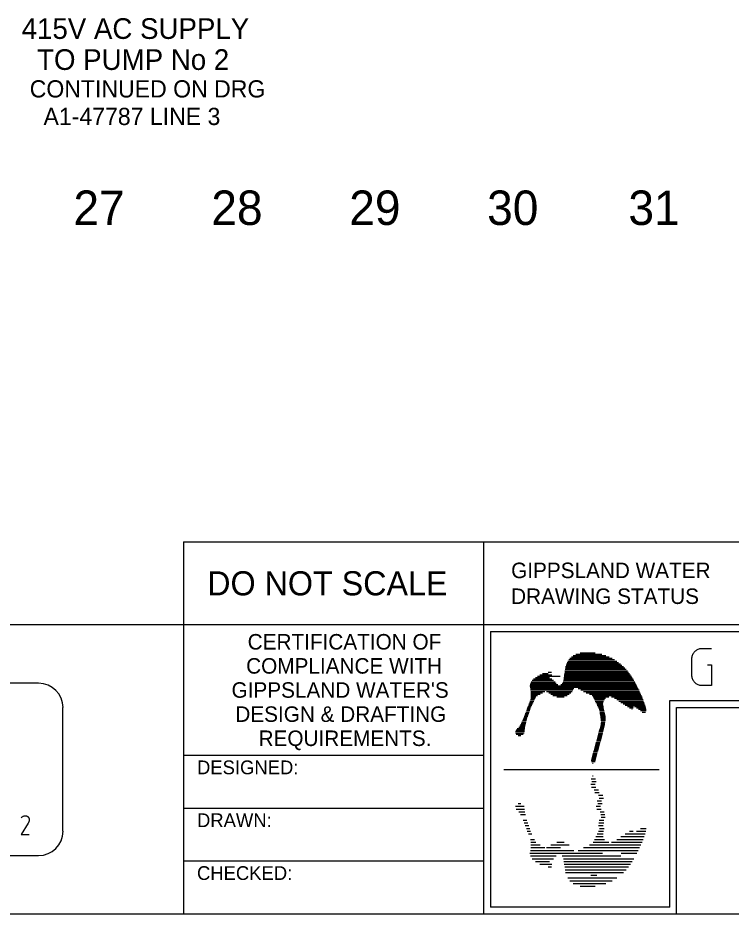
# Model space of a CAD drawing. Extents: x 0 to 841, y 0 to 594.
# Drawn here: x 568.5 to 671.9, y 15 to 145 of the extents above; entities that cross this region are included whole.
import ezdxf

# ---------------------------------------------------------------- set-up
doc = ezdxf.new("R2010")
doc.units = 0
for name, color, linetype in [('A1BORDER', 7, 'Continuous'), ('Level 1', 7, 'Continuous'), ('Level 10', 7, 'Continuous')]:
    doc.layers.add(name, color=color, linetype=linetype)

msp = doc.modelspace()

# ---------------------------------------------------------------- linework, layer by layer
at = {"layer": 'A1BORDER'}
for p, q in [((592.5, 69), (592.5, 15)), ((592.5, 69), (829, 69)), ((636, 69), (636, 15)), ((28, 57), (829, 57)), ((637, 56), (788, 56)), ((637, 56), (637, 16)), ((648.53, 52.12), (654.64, 52.12)), ((648.74, 52.32), (654.24, 52.32)), ((649.02, 52.52), (653.76, 52.52)), ((649.39, 52.72), (653.15, 52.72)), ((650.01, 52.92), (652.2, 52.92)), ((647.88, 50.72), (656.5, 50.72)), ((647.91, 50.92), (656.3, 50.92)), ((647.96, 51.12), (656.08, 51.12)), ((648.03, 51.32), (655.85, 51.32)), ((648.12, 51.52), (655.59, 51.52)), ((648.23, 51.72), (655.31, 51.72)), ((648.37, 51.92), (655, 51.92)), ((643.85, 49.52), (647.09, 49.52)), ((644.18, 49.72), (645.89, 49.72)), ((644.54, 49.92), (645.36, 49.92)), ((645.37, 50.12), (645.86, 50.12)), ((647.69, 49.52), (657.44, 49.52)), ((647.71, 49.72), (657.31, 49.72)), ((647.75, 49.92), (657.17, 49.92)), ((647.78, 50.12), (657.02, 50.12)), ((647.81, 50.32), (656.86, 50.32)), ((647.85, 50.52), (656.69, 50.52)), ((642.73, 48.12), (658.25, 48.12)), ((642.75, 48.32), (646.79, 48.32)), ((642.81, 48.52), (646.55, 48.52)), ((642.9, 48.72), (646.37, 48.72)), ((643.04, 48.92), (646.16, 48.92)), ((643.26, 49.12), (645.9, 49.12)), ((643.54, 49.32), (645.57, 49.32)), ((647.19, 48.32), (658.14, 48.32)), ((647.42, 48.52), (658.03, 48.52)), ((647.54, 48.72), (657.92, 48.72)), ((647.61, 48.92), (657.8, 48.92)), ((647.63, 49.12), (657.68, 49.12)), ((647.66, 49.32), (657.57, 49.32)), ((642.74, 47.92), (658.35, 47.92)), ((642.79, 47.72), (649.08, 47.72)), ((642.83, 47.52), (648.95, 47.52)), ((642.85, 47.31), (644.88, 47.31)), ((642.87, 47.12), (644.57, 47.12)), ((642.88, 46.92), (644.23, 46.92)), ((645.14, 47.31), (648.83, 47.31)), ((645.49, 47.12), (648.67, 47.12)), ((645.76, 46.92), (648.42, 46.92)), ((649.72, 47.72), (658.45, 47.72)), ((650.12, 47.52), (658.55, 47.52)), ((650.48, 47.31), (658.64, 47.31)), ((650.87, 47.12), (658.73, 47.12)), ((651.36, 46.92), (658.82, 46.92)), ((642.57, 45.52), (643.1, 45.52)), ((642.65, 45.72), (643.2, 45.72)), ((642.72, 45.92), (643.3, 45.92)), ((642.79, 46.12), (643.4, 46.12)), ((642.84, 46.32), (643.5, 46.32)), ((642.87, 46.52), (643.6, 46.52)), ((642.88, 46.72), (643.83, 46.72)), ((646.05, 46.72), (648.11, 46.72)), ((646.62, 46.52), (647.67, 46.52)), ((651.76, 46.72), (658.9, 46.72)), ((651.88, 46.52), (654.15, 46.52)), ((651.99, 46.32), (653.71, 46.32)), ((652.1, 46.12), (653.52, 46.12)), ((652.2, 45.92), (653.4, 45.92)), ((652.31, 45.72), (653.33, 45.72)), ((652.41, 45.52), (653.31, 45.52)), ((654.57, 46.52), (658.99, 46.52)), ((655, 46.32), (659.07, 46.32)), ((655.31, 46.12), (659.14, 46.12)), ((655.62, 45.92), (659.22, 45.92)), ((655.93, 45.72), (659.29, 45.72)), ((656.24, 45.52), (659.35, 45.52)), ((663, 46), (788, 46)), ((663, 16), (663, 46)), ((642.13, 44.32), (642.62, 44.32)), ((642.21, 44.52), (642.69, 44.52)), ((642.28, 44.72), (642.76, 44.72)), ((642.35, 44.92), (642.83, 44.92)), ((642.43, 45.12), (642.9, 45.12)), ((642.5, 45.32), (643, 45.32)), ((652.5, 45.32), (653.34, 45.32)), ((652.6, 45.12), (653.38, 45.12)), ((652.69, 44.92), (653.41, 44.92)), ((652.78, 44.72), (653.44, 44.72)), ((652.83, 44.52), (653.48, 44.52)), ((652.86, 44.32), (653.53, 44.32)), ((656.55, 45.32), (659.42, 45.32)), ((656.86, 45.12), (657.74, 45.12)), ((657.17, 44.92), (657.68, 44.92)), ((657.51, 44.72), (657.54, 44.72)), ((657.91, 45.12), (659.48, 45.12)), ((658.19, 44.92), (659.54, 44.92)), ((658.47, 44.72), (659.59, 44.72)), ((658.75, 44.52), (659.58, 44.52)), ((659.02, 44.32), (659.47, 44.32)), ((664, 45), (829, 45)), ((664, 15), (664, 45)), ((641.55, 42.92), (642.2, 42.92)), ((641.64, 43.12), (642.25, 43.12)), ((641.73, 43.32), (642.3, 43.32)), ((641.82, 43.51), (642.35, 43.51)), ((641.91, 43.72), (642.41, 43.72)), ((641.99, 43.92), (642.48, 43.92)), ((642.06, 44.12), (642.55, 44.12)), ((652.89, 44.12), (653.57, 44.12)), ((652.91, 43.92), (653.62, 43.92)), ((652.94, 43.72), (653.67, 43.72)), ((652.97, 43.51), (653.71, 43.51)), ((653, 43.32), (653.69, 43.32)), ((653.02, 43.12), (653.67, 43.12)), ((653.05, 42.92), (653.64, 42.92)), ((640.73, 41.72), (641.95, 41.72)), ((640.9, 41.92), (641.97, 41.92)), ((641.1, 42.12), (642, 42.12)), ((641.25, 42.31), (642.04, 42.31)), ((641.37, 42.52), (642.09, 42.52)), ((641.46, 42.72), (642.15, 42.72)), ((652.79, 41.72), (653.41, 41.72)), ((652.85, 41.92), (653.45, 41.92)), ((652.9, 42.12), (653.49, 42.12)), ((652.95, 42.31), (653.53, 42.31)), ((652.99, 42.52), (653.57, 42.52)), ((653.03, 42.72), (653.61, 42.72)), ((640.62, 41.32), (641.88, 41.32)), ((640.63, 41.52), (641.93, 41.52)), ((640.72, 41.12), (641.73, 41.12)), ((641.03, 40.92), (641.43, 40.92)), ((652.41, 40.32), (653.04, 40.32)), ((652.47, 40.52), (653.1, 40.52)), ((652.52, 40.72), (653.15, 40.72)), ((652.57, 40.92), (653.2, 40.92)), ((652.63, 41.12), (653.26, 41.12)), ((652.68, 41.32), (653.31, 41.32)), ((652.74, 41.52), (653.37, 41.52)), ((652.09, 39.12), (652.72, 39.12)), ((652.14, 39.32), (652.77, 39.32)), ((652.2, 39.52), (652.82, 39.52)), ((652.25, 39.72), (652.88, 39.72)), ((652.3, 39.92), (652.93, 39.92)), ((652.36, 40.12), (652.99, 40.12)), ((636, 38), (592.5, 38)), ((651.71, 37.72), (652.34, 37.72)), ((651.76, 37.92), (652.39, 37.92)), ((651.82, 38.12), (652.44, 38.12)), ((651.87, 38.32), (652.5, 38.32)), ((651.92, 38.52), (652.55, 38.52)), ((651.98, 38.72), (652.61, 38.72)), ((652.03, 38.92), (652.66, 38.92)), ((651.63, 37.32), (652.23, 37.32)), ((651.64, 37.12), (652.17, 37.12)), ((651.65, 37.52), (652.28, 37.52)), ((651.79, 36.92), (651.9, 36.92)), ((638.93, 35.98), (661.47, 35.98)), ((651.54, 33.84), (652.17, 33.84)), ((651.63, 34.64), (652.23, 34.64)), ((651.71, 34.24), (652.34, 34.24)), ((651.79, 35.04), (651.9, 35.04)), ((651.65, 33.44), (652.28, 33.44)), ((652.03, 33.04), (652.66, 33.04)), ((652.14, 32.64), (652.77, 32.64)), ((652.47, 31.44), (653.1, 31.44)), ((652.66, 32.24), (653.29, 32.24)), ((652.77, 31.84), (653.4, 31.84)), ((636, 30.34), (592.5, 30.34)), ((640.62, 30.64), (641.88, 30.64)), ((640.73, 30.24), (641.95, 30.24)), ((641.03, 31.04), (641.43, 31.04)), ((652.34, 30.64), (652.97, 30.64)), ((652.45, 30.24), (653.07, 30.24)), ((652.57, 31.04), (653.2, 31.04)), ((641.1, 29.84), (642, 29.84)), ((641.37, 29.44), (642.09, 29.44)), ((641.73, 28.64), (642.3, 28.64)), ((652.77, 28.64), (653.46, 28.64)), ((652.9, 29.84), (653.49, 29.84)), ((652.99, 29.44), (653.57, 29.44)), ((653.05, 29.04), (653.64, 29.04)), ((641.91, 28.24), (642.41, 28.24)), ((642.06, 27.84), (642.55, 27.84)), ((642.21, 27.44), (642.69, 27.44)), ((652.66, 27.84), (653.35, 27.84)), ((652.72, 28.24), (653.44, 28.24)), ((652.83, 27.44), (653.48, 27.44)), ((658.75, 27.44), (659.58, 27.44)), ((642.35, 27.04), (642.83, 27.04)), ((642.5, 26.64), (643, 26.64)), ((652.31, 26.24), (653.33, 26.24)), ((652.5, 26.64), (653.34, 26.64)), ((652.69, 27.04), (653.41, 27.04)), ((655.93, 26.24), (659.29, 26.24)), ((656.55, 26.64), (659.42, 26.64)), ((657.17, 27.04), (657.68, 27.04)), ((658.19, 27.04), (659.54, 27.04)), ((642.79, 25.84), (643.4, 25.84)), ((642.87, 25.44), (643.6, 25.44)), ((642.88, 25.04), (644.23, 25.04)), ((645.76, 25.04), (648.42, 25.04)), ((646.62, 25.44), (647.67, 25.44)), ((651.36, 25.04), (658.82, 25.04)), ((651.88, 25.44), (654.15, 25.44)), ((652.1, 25.84), (653.52, 25.84)), ((654.57, 25.44), (658.99, 25.44)), ((655.31, 25.84), (659.14, 25.84)), ((642.73, 23.84), (653.27, 23.84)), ((642.79, 24.24), (649.08, 24.24)), ((642.81, 23.44), (646.55, 23.44)), ((642.85, 24.65), (644.88, 24.65)), ((645.14, 24.65), (647.18, 24.65)), ((647.42, 23.44), (655.89, 23.44)), ((649.72, 24.24), (658.45, 24.24)), ((650.48, 24.65), (658.64, 24.65)), ((655.94, 23.84), (658.25, 23.84)), ((636, 22.67), (592.5, 22.67)), ((643.04, 23.04), (646.16, 23.04)), ((643.54, 22.64), (645.57, 22.64)), ((644.18, 22.24), (645.89, 22.24)), ((647.61, 23.04), (657.8, 23.04)), ((647.66, 22.64), (657.57, 22.64)), ((647.71, 22.24), (657.31, 22.24)), ((645.37, 21.84), (645.86, 21.84)), ((647.78, 21.84), (657.02, 21.84)), ((647.85, 21.44), (656.69, 21.44)), ((647.91, 21.04), (656.3, 21.04)), ((648.23, 20.24), (655.31, 20.24)), ((648.53, 19.84), (654.64, 19.84)), ((651.57, 20.64), (652.44, 20.64)), ((649.02, 19.44), (653.76, 19.44)), ((650.01, 19.04), (652.2, 19.04)), ((663, 16), (637, 16)), ((829, 15), (28, 15))]:
    msp.add_line(p, q, dxfattribs=at)
msp.add_lwpolyline([(668.49, 51.15), (669.06, 51.15), (669.06, 48.16), (667.64, 48.16), (667.51, 48.16), (667.39, 48.18), (667.28, 48.21), (667.15, 48.25), (667.04, 48.3), (666.93, 48.36), (666.82, 48.43), (666.73, 48.51), (666.64, 48.6), (666.55, 48.7), (666.48, 48.8), (666.41, 48.91), (666.35, 49.02), (666.31, 49.14), (666.27, 49.27), (666.24, 49.39), (666.22, 49.52), (666.22, 49.66), (666.22, 52.05), (666.22, 52.18), (666.24, 52.31), (666.27, 52.43), (666.31, 52.56), (666.35, 52.67), (666.41, 52.79), (666.48, 52.9), (666.55, 53), (666.64, 53.1), (666.73, 53.19), (666.82, 53.27), (666.93, 53.34), (667.04, 53.4), (667.15, 53.45), (667.28, 53.49), (667.39, 53.52), (667.51, 53.54), (667.64, 53.54), (669.06, 53.54)], dxfattribs=at)
at = {"layer": 'Level 1'}
msp.add_lwpolyline([(568.92, 28.96), (568.97, 29.01), (569.02, 29.07), (569.08, 29.11), (569.16, 29.15), (569.22, 29.19), (569.29, 29.21), (569.37, 29.24), (569.44, 29.25), (569.52, 29.26), (569.56, 29.26), (569.6, 29.26), (569.66, 29.25), (569.7, 29.24), (569.76, 29.23), (569.79, 29.21), (569.84, 29.19), (569.88, 29.16), (569.92, 29.13), (569.96, 29.1), (569.98, 29.05), (570.02, 29.01), (570.04, 28.97), (570.06, 28.94), (570.08, 28.89), (570.09, 28.84), (570.1, 28.79), (570.1, 28.75), (570.1, 28.7), (570.1, 28.66), (570.09, 28.57), (570.08, 28.5), (570.06, 28.43), (570.03, 28.35), (569.99, 28.27), (569.96, 28.21), (568.92, 26.57), (570.1, 26.57)], dxfattribs=at)
at = {"layer": 'Level 10'}
for p, q in [((571.47, 48.5), (513.54, 48.5)), ((575, 27.03), (575, 44.97)), ((513.54, 23.5), (571.47, 23.5))]:
    msp.add_line(p, q, dxfattribs=at)
for centre, start, end in [((571.47, 44.96), 0, 90), ((571.47, 27.03), 270, 0)]:
    msp.add_arc(centre, 3.54, start, end, dxfattribs=at)

# ---------------------------------------------------------------- texts
at = {"layer": 'A1BORDER'}
for s, height, p in [('GIPPSLAND WATER', 2.25, (640, 63.75)), ('DO NOT SCALE', 3.5, (595.92, 61.25)), ('DRAWING STATUS', 2.25, (640, 60)), ('CERTIFICATION OF', 2.25, (601.79, 53.39)), ('COMPLIANCE WITH', 2.25, (601.57, 49.89)), ("GIPPSLAND WATER'S", 2.25, (599.45, 46.39)), ('DESIGN & DRAFTING', 2.25, (600, 42.89)), ('REQUIREMENTS.', 2.25, (603.37, 39.39)), ('DESIGNED:', 2, (594.44, 35.29)), ('DRAWN:', 2, (594.44, 27.62)), ('CHECKED:', 2, (594.44, 19.95))]:
    msp.add_text(s, height=height, dxfattribs=at).set_placement(p)
at = {"layer": 'Level 1'}
for s, height, p in [('415V AC SUPPLY', 3, (569.01, 142)), ('TO PUMP No 2', 3, (571.25, 137.5)), ('CONTINUED ON DRG', 2.5, (570.18, 133.5)), ('A1-47787 LINE 3', 2.5, (572.18, 129.5)), ('27', 5, (576.52, 115)), ('28', 5, (596.52, 115)), ('29', 5, (616.52, 115)), ('30', 5, (636.52, 115)), ('31', 5, (657.01, 115))]:
    msp.add_text(s, height=height, dxfattribs=at).set_placement(p)

doc.saveas('drawing.dxf')
